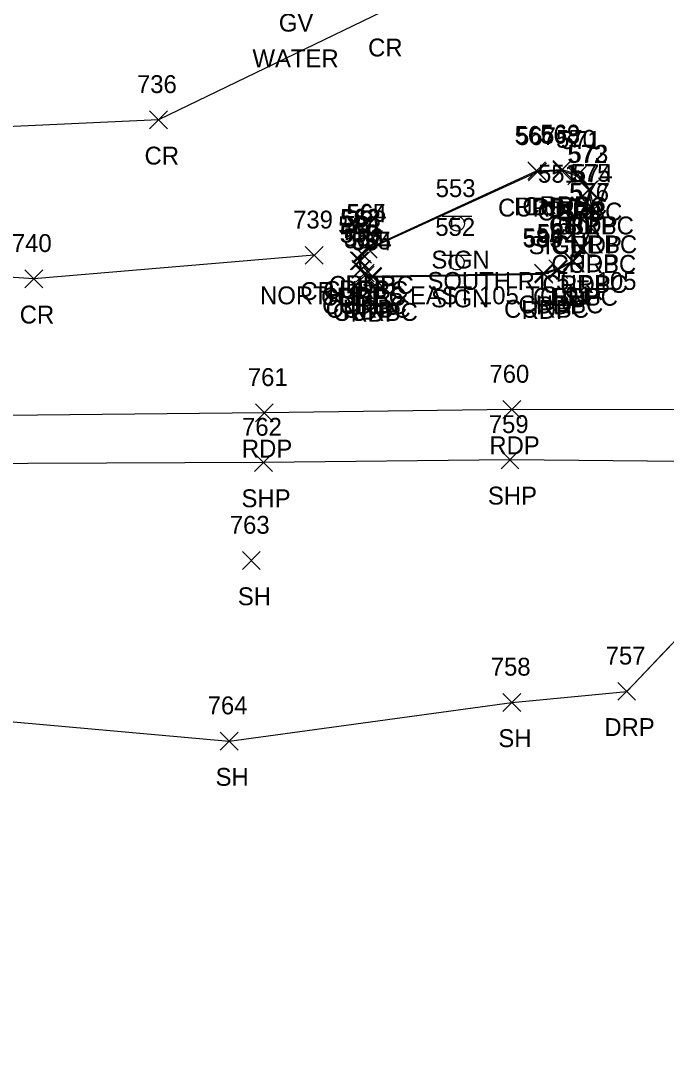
# Model space of a CAD drawing. Extents: x 1715662 to 1717487, y 887396 to 890004.
# Drawn here: x 1716519.9 to 1716592.1, y 888134.9 to 888252.4 of the extents above; entities that cross this region are included whole.
import ezdxf

# ---------------------------------------------------------------- set-up
doc = ezdxf.new("R2010")
doc.units = 0
for name, color, linetype in [('L_A', 7, 'Continuous'), ('L_I', 7, 'Continuous'), ('L_TIC', 7, 'Continuous'), ('LSOGP', 7, 'Continuous'), ('P_A', 7, 'Continuous'), ('P_I', 7, 'Continuous'), ('P_TIC', 7, 'Continuous'), ('PET', 7, 'Continuous'), ('PRC', 7, 'Continuous'), ('PSP', 7, 'Continuous'), ('R_A', 7, 'Continuous'), ('R_I', 7, 'Continuous'), ('R_TIC', 7, 'Continuous'), ('RC', 7, 'Continuous'), ('RDP', 7, 'Continuous'), ('S_A', 7, 'Continuous'), ('S_C', 7, 'Continuous'), ('S_I', 7, 'Continuous'), ('SSGN', 7, 'Continuous'), ('U_A', 7, 'Continuous'), ('U_C', 7, 'Continuous')]:
    doc.layers.add(name, color=color, linetype=linetype)

msp = doc.modelspace()

# ---------------------------------------------------------------- linework, layer by layer
at = {"layer": 'L_TIC'}
for points in [[(1716544.67, 888191), (1716546.67, 888193)], [(1716546.67, 888191), (1716544.67, 888193)], [(1716573.85, 888175.12), (1716575.85, 888177.12)], [(1716575.85, 888175.12), (1716573.85, 888177.12)], [(1716542.19, 888170.79), (1716544.19, 888172.79)], [(1716544.19, 888170.79), (1716542.19, 888172.79)]]:
    msp.add_lwpolyline(points, dxfattribs=at)
at = {"layer": 'LSOGP'}
msp.add_lwpolyline([(1716495.94, 888131.85), (1716495.88, 888137.11), (1716495.83, 888142.38), (1716495.77, 888147.64), (1716511.9, 888174.6), (1716543.19, 888171.79), (1716574.85, 888176.12), (1716587.72, 888177.36), (1716591.77, 888181.6), (1716595.82, 888185.85), (1716600.22, 888185.86), (1716640.78, 888181.27), (1716639.39, 888169.56), (1716653.42, 888168.34), (1716667.9, 888172.89), (1716689.55, 888170.91), (1716693.25, 888191.71), (1716736.98, 888184.04)], dxfattribs=at)
at = {"layer": 'P_TIC'}
for points in [[(1716534.28, 888240.32), (1716536.28, 888242.32)], [(1716536.28, 888240.32), (1716534.28, 888242.32)], [(1716576.63, 888234.63), (1716578.63, 888236.63)], [(1716578.63, 888234.63), (1716576.63, 888236.63)], [(1716579.48, 888234.78), (1716581.48, 888236.78)], [(1716581.48, 888234.78), (1716579.48, 888236.78)], [(1716581.25, 888234.2), (1716583.25, 888236.2)], [(1716583.25, 888234.2), (1716581.25, 888236.2)], [(1716582.55, 888232.53), (1716584.55, 888234.53)], [(1716584.55, 888232.53), (1716582.55, 888234.53)], [(1716583.04, 888230.34), (1716585.04, 888232.34)], [(1716585.04, 888230.34), (1716583.04, 888232.34)], [(1716582.72, 888228.27), (1716584.72, 888230.27)], [(1716584.72, 888228.27), (1716582.72, 888230.27)], [(1716551.72, 888225.16), (1716553.72, 888227.16)], [(1716553.72, 888225.16), (1716551.72, 888227.16)], [(1716557.02, 888225.36), (1716559.02, 888227.36)], [(1716559.02, 888225.36), (1716557.02, 888227.36)], [(1716557.72, 888225.92), (1716559.72, 888227.92)], [(1716559.72, 888225.92), (1716557.72, 888227.92)], [(1716581.79, 888225.91), (1716583.79, 888227.91)], [(1716583.79, 888225.91), (1716581.79, 888227.91)], [(1716556.76, 888224.55), (1716558.76, 888226.55)], [(1716558.76, 888224.55), (1716556.76, 888226.55)], [(1716580.75, 888224.5), (1716582.75, 888226.5)], [(1716582.75, 888224.5), (1716580.75, 888226.5)], [(1716556.93, 888223.6), (1716558.93, 888225.6)], [(1716558.93, 888223.6), (1716556.93, 888225.6)], [(1716557.43, 888222.95), (1716559.43, 888224.95)], [(1716559.43, 888222.95), (1716557.43, 888224.95)], [(1716558.3, 888222.72), (1716560.3, 888224.72)], [(1716560.3, 888222.72), (1716558.3, 888224.72)], [(1716558.3, 888222.72), (1716560.3, 888224.72)], [(1716560.3, 888222.72), (1716558.3, 888224.72)], [(1716577.45, 888223.05), (1716579.45, 888225.05)], [(1716579.45, 888223.05), (1716577.45, 888225.05)], [(1716577.45, 888223.05), (1716579.45, 888225.05)], [(1716579.45, 888223.05), (1716577.45, 888225.05)], [(1716579.07, 888223.57), (1716581.07, 888225.57)], [(1716581.07, 888223.57), (1716579.07, 888225.57)], [(1716520.3, 888222.53), (1716522.3, 888224.53)], [(1716522.3, 888222.53), (1716520.3, 888224.53)], [(1716546.13, 888207.53), (1716548.13, 888209.53)], [(1716548.13, 888207.53), (1716546.13, 888209.53)], [(1716573.84, 888207.9), (1716575.84, 888209.9)], [(1716575.84, 888207.9), (1716573.84, 888209.9)], [(1716546.04, 888201.97), (1716548.04, 888203.97)], [(1716548.04, 888201.97), (1716546.04, 888203.97)], [(1716573.64, 888202.27), (1716575.64, 888204.27)], [(1716575.64, 888202.27), (1716573.64, 888204.27)]]:
    msp.add_lwpolyline(points, dxfattribs=at)
at = {"layer": 'PET'}
for points in [[(1716559.3, 888223.72), (1716558.43, 888223.95), (1716557.93, 888224.6), (1716557.76, 888225.55), (1716558.02, 888226.36), (1716558.72, 888226.92), (1716577.63, 888235.63), (1716580.48, 888235.78), (1716582.25, 888235.2), (1716583.55, 888233.53), (1716584.04, 888231.34), (1716583.72, 888229.27), (1716582.79, 888226.91), (1716581.75, 888225.5), (1716580.07, 888224.57), (1716578.45, 888224.05)], [(1716559.3, 888223.72), (1716578.45, 888224.05)], [(1716662.11, 888208.93), (1716631.8, 888208.17), (1716598.77, 888208.88), (1716574.84, 888208.9), (1716547.13, 888208.53), (1716499.86, 888208.03), (1716470.5, 888209.82), (1716470.57, 888209.92), (1716434.17, 888214.11), (1716420.85, 888214.16)]]:
    msp.add_lwpolyline(points, dxfattribs=at)
at = {"layer": 'PRC'}
for points in [[(1716612.85, 888359.68), (1716612.17, 888345.49), (1716610.23, 888325.05), (1716599.91, 888295.77), (1716584.78, 888274.26), (1716560.31, 888253.42), (1716535.28, 888241.32), (1716471.98, 888238.42), (1716446.91, 888240.45), (1716423.44, 888242.23), (1716395.99, 888243.46), (1716360.07, 888243.38), (1716329.01, 888242.88), (1716285.79, 888240.52), (1716253.17, 888237.3), (1716220.47, 888232.04), (1716184.13, 888222.3), (1716155.75, 888211.83), (1716125.79, 888199.82), (1716096.66, 888186.57)], [(1716552.72, 888226.16), (1716521.3, 888223.53), (1716490.76, 888225.55), (1716471.3, 888227.05), (1716451.95, 888228.65), (1716428.34, 888230.29), (1716394.24, 888231.4), (1716360.6, 888231.76), (1716326.71, 888231.11), (1716290.95, 888229.37), (1716251.51, 888225.94), (1716222.8, 888221), (1716188.27, 888210.85), (1716159.49, 888199.86), (1716131.41, 888188.25), (1716103, 888175.83)]]:
    msp.add_lwpolyline(points, dxfattribs=at)
at = {"layer": 'PSP'}
msp.add_lwpolyline([(1716661.99, 888204.6), (1716631.89, 888203.79), (1716597.76, 888203.06), (1716574.64, 888203.27), (1716547.04, 888202.97), (1716494.19, 888202.74), (1716493.66, 888200.18), (1716489.19, 888200.69), (1716470.28, 888201.06), (1716436.75, 888202.98), (1716426.58, 888205.04), (1716425.59, 888209.88)], dxfattribs=at)
at = {"layer": 'R_TIC'}
for points in [[(1716576.73, 888234.5), (1716578.73, 888236.5)], [(1716578.73, 888234.5), (1716576.73, 888236.5)], [(1716579.43, 888234.66), (1716581.43, 888236.66)], [(1716581.43, 888234.66), (1716579.43, 888236.66)], [(1716581.14, 888234.06), (1716583.14, 888236.06)], [(1716583.14, 888234.06), (1716581.14, 888236.06)], [(1716582.43, 888232.5), (1716584.43, 888234.5)], [(1716584.43, 888232.5), (1716582.43, 888234.5)], [(1716582.79, 888230.4), (1716584.79, 888232.4)], [(1716584.79, 888230.4), (1716582.79, 888232.4)], [(1716582.69, 888228.2), (1716584.69, 888230.2)], [(1716584.69, 888228.2), (1716582.69, 888230.2)], [(1716557.13, 888225.28), (1716559.13, 888227.28)], [(1716559.13, 888225.28), (1716557.13, 888227.28)], [(1716557.77, 888225.85), (1716559.77, 888227.85)], [(1716559.77, 888225.85), (1716557.77, 888227.85)], [(1716581.69, 888225.96), (1716583.69, 888227.96)], [(1716583.69, 888225.96), (1716581.69, 888227.96)], [(1716556.9, 888224.54), (1716558.9, 888226.54)], [(1716558.9, 888224.54), (1716556.9, 888226.54)], [(1716580.63, 888224.52), (1716582.63, 888226.52)], [(1716582.63, 888224.52), (1716580.63, 888226.52)], [(1716557.02, 888223.59), (1716559.02, 888225.59)], [(1716559.02, 888223.59), (1716557.02, 888225.59)], [(1716557.42, 888223.18), (1716559.42, 888225.18)], [(1716559.42, 888223.18), (1716557.42, 888225.18)], [(1716558.23, 888222.82), (1716560.23, 888224.82)], [(1716560.23, 888222.82), (1716558.23, 888224.82)], [(1716558.23, 888222.82), (1716560.23, 888224.82)], [(1716560.23, 888222.82), (1716558.23, 888224.82)], [(1716577.4, 888223.17), (1716579.4, 888225.17)], [(1716579.4, 888223.17), (1716577.4, 888225.17)], [(1716577.4, 888223.17), (1716579.4, 888225.17)], [(1716579.4, 888223.17), (1716577.4, 888225.17)], [(1716579, 888223.67), (1716581, 888225.67)], [(1716581, 888223.67), (1716579, 888225.67)], [(1716586.72, 888176.36), (1716588.72, 888178.36)], [(1716588.72, 888176.36), (1716586.72, 888178.36)]]:
    msp.add_lwpolyline(points, dxfattribs=at)
at = {"layer": 'RC'}
for points in [[(1716559.23, 888223.82), (1716558.42, 888224.18), (1716558.02, 888224.59), (1716557.9, 888225.54), (1716558.13, 888226.28), (1716558.77, 888226.85), (1716577.73, 888235.5), (1716580.43, 888235.66), (1716582.14, 888235.06), (1716583.43, 888233.5), (1716583.79, 888231.4), (1716583.69, 888229.2), (1716582.69, 888226.96), (1716581.63, 888225.52), (1716580, 888224.67), (1716578.4, 888224.17)], [(1716559.23, 888223.82), (1716578.4, 888224.17)]]:
    msp.add_lwpolyline(points, dxfattribs=at)
at = {"layer": 'RDP'}
msp.add_lwpolyline([(1716600.22, 888185.86), (1716595.82, 888185.85), (1716587.72, 888177.36)], dxfattribs=at)
at = {"layer": 'SSGN'}
for p, q in [((1716577.95, 888232.14), (1716581.28, 888232.14)), ((1716567.05, 888230.53), (1716570.38, 888230.53)), ((1716579.59, 888231.31), (1716579.59, 888231.31)), ((1716568.7, 888229.7), (1716568.7, 888229.7)), ((1716567.01, 888226.19), (1716570.35, 888226.19)), ((1716568.66, 888225.36), (1716568.66, 888225.36))]:
    msp.add_line(p, q, dxfattribs=at)
for centre in [(1716579.59, 888231.31), (1716568.7, 888229.7), (1716568.66, 888225.36)]:
    msp.add_circle(centre, 0.833, dxfattribs=at)

# ---------------------------------------------------------------- texts
at = {"layer": 'L_A'}
for p in [(1716544.16, 888187), (1716573.34, 888171.12), (1716541.67, 888166.79)]:
    msp.add_text('SH', height=2, dxfattribs=at).set_placement(p)
at = {"layer": 'L_I'}
for s, p in [('763', (1716543.26, 888195)), ('758', (1716572.49, 888179.12)), ('764', (1716540.78, 888174.79))]:
    msp.add_text(s, height=2, dxfattribs=at).set_placement(p)
at = {"layer": 'P_A'}
for s, p in [('CR', (1716558.75, 888248.42)), ('CR', (1716533.71, 888236.32)), ('RDP', (1716575.11, 888230.63)), ('RDP', (1716577.97, 888230.78)), ('RDP', (1716579.74, 888230.2)), ('RDP', (1716581.04, 888228.53)), ('RDP', (1716581.53, 888226.34)), ('RDP', (1716581.21, 888224.27)), ('RDP', (1716556.21, 888221.92)), ('RDP', (1716580.28, 888221.91)), ('CR', (1716551.16, 888221.16)), ('RDP', (1716555.25, 888220.55)), ('RDP', (1716555.51, 888221.36)), ('RDP', (1716579.24, 888220.5)), ('RDP', (1716555.41, 888219.6)), ('RDP', (1716577.56, 888219.57)), ('CR', (1716519.73, 888218.53)), ('RDP', (1716555.92, 888218.95)), ('RDP', (1716556.79, 888218.72)), ('RDP', (1716556.79, 888218.72)), ('RDP', (1716575.94, 888219.05)), ('RDP', (1716575.94, 888219.05)), ('RDP', (1716572.33, 888203.9)), ('RDP', (1716544.61, 888203.53)), ('SHP', (1716544.57, 888197.97)), ('SHP', (1716572.17, 888198.27))]:
    msp.add_text(s, height=2, dxfattribs=at).set_placement(p)
at = {"layer": 'P_I'}
for s, p in [('736', (1716532.86, 888244.32)), ('566', (1716575.16, 888238.63)), ('569', (1716578.06, 888238.78)), ('570', (1716579.8, 888238.2)), ('573', (1716581.19, 888236.53)), ('574', (1716581.67, 888234.34)), ('577', (1716581.36, 888232.27)), ('565', (1716556.31, 888229.92)), ('578', (1716580.43, 888229.91)), ('739', (1716550.35, 888229.16)), ('562', (1716555.61, 888229.36)), ('561', (1716555.92, 888228.55)), ('581', (1716579.96, 888228.5)), ('558', (1716555.56, 888227.6)), ('582', (1716577.71, 888227.57)), ('740', (1716518.85, 888226.53)), ('557', (1716556.07, 888226.95)), ('554', (1716556.94, 888226.72)), ('554', (1716556.94, 888226.72)), ('585', (1716576.09, 888227.05)), ('585', (1716576.09, 888227.05)), ('761', (1716545.28, 888211.53)), ('760', (1716572.34, 888211.9)), ('759', (1716572.27, 888206.27)), ('762', (1716544.63, 888205.97))]:
    msp.add_text(s, height=2, dxfattribs=at).set_placement(p)
at = {"layer": 'R_A'}
for s, p in [('CURBC', (1716573.31, 888230.5)), ('CURBC', (1716576.02, 888230.66)), ('CURBC', (1716577.72, 888230.06)), ('CURBC', (1716579.01, 888228.5)), ('CURBC', (1716579.38, 888226.4)), ('CURBC', (1716579.27, 888224.2)), ('CURBC', (1716554.35, 888221.85)), ('CURBC', (1716578.28, 888221.96)), ('CURBC', (1716553.48, 888220.54)), ('CURBC', (1716553.72, 888221.28)), ('CURBC', (1716577.22, 888220.52)), ('CURBC', (1716553.6, 888219.59)), ('CURBC', (1716554, 888219.18)), ('CURBC', (1716573.98, 888219.17)), ('CURBC', (1716573.98, 888219.17)), ('CURBC', (1716575.59, 888219.67)), ('CURBC', (1716554.81, 888218.82)), ('CURBC', (1716554.81, 888218.82)), ('DRP', (1716585.21, 888172.36))]:
    msp.add_text(s, height=2, dxfattribs=at).set_placement(p)
at = {"layer": 'R_I'}
for s, p in [('567', (1716575.32, 888238.5)), ('568', (1716578.02, 888238.66)), ('571', (1716580.34, 888238.06)), ('572', (1716581.07, 888236.5)), ('575', (1716581.43, 888234.4)), ('576', (1716581.27, 888232.2)), ('564', (1716556.36, 888229.85)), ('579', (1716580.32, 888229.96)), ('560', (1716555.4, 888228.54)), ('563', (1716555.72, 888229.28)), ('580', (1716579.18, 888228.52)), ('559', (1716555.65, 888227.59)), ('583', (1716577.64, 888227.67)), ('556', (1716556, 888227.18)), ('555', (1716556.87, 888226.82)), ('555', (1716556.87, 888226.82)), ('584', (1716576.04, 888227.17)), ('584', (1716576.04, 888227.17)), ('757', (1716585.36, 888180.36))]:
    msp.add_text(s, height=2, dxfattribs=at).set_placement(p)
at = {"layer": 'S_A'}
for p in [(1716576.73, 888226.29), (1716565.84, 888224.68), (1716565.8, 888220.34)]:
    msp.add_text('SIGN', height=2, dxfattribs=at).set_placement(p)
at = {"layer": 'S_C'}
for s, p in [('SOUTH RT 5 + 105', (1716565.4, 888222.29)), ('NORTH RT 5 EAST 105 TO 91', (1716546.65, 888220.68))]:
    msp.add_text(s, height=2, dxfattribs=at).set_placement(p)
at = {"layer": 'S_I'}
for s, p in [('551', (1716577.78, 888234.29)), ('553', (1716566.32, 888232.68)), ('552', (1716566.28, 888228.34))]:
    msp.add_text(s, height=2, dxfattribs=at).set_placement(p)
at = {"layer": 'U_A'}
msp.add_text('GV', height=2, dxfattribs=at).set_placement((1716548.75, 888251.2))
at = {"layer": 'U_C'}
msp.add_text('WATER', height=2, dxfattribs=at).set_placement((1716545.8, 888247.2))

doc.saveas('drawing.dxf')
